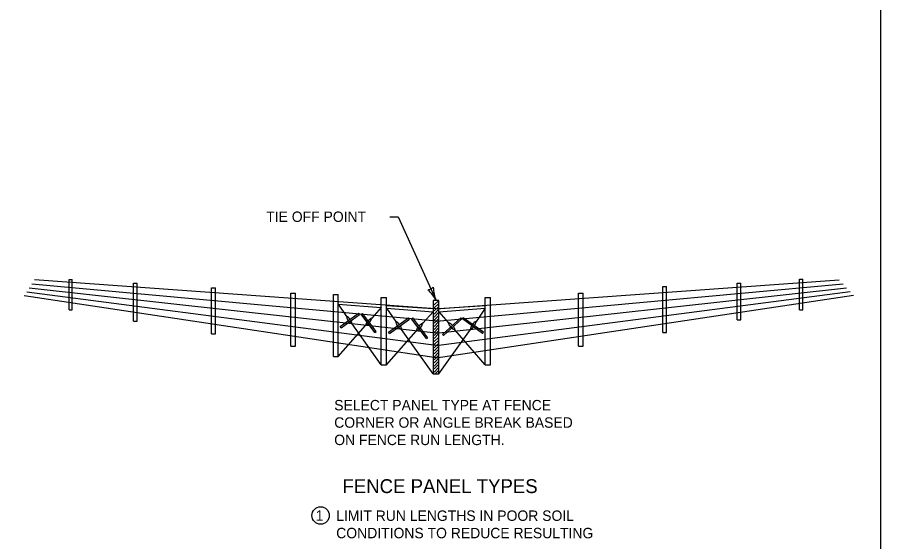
# Model space of a CAD drawing. Extents: x 49990.8 to 50021, y 49987.6 to 50011.4.
# Drawn here: x 50003.644 to 50008.615, y 50005.224 to 50008.243 of the extents above; entities that cross this region are included whole.
import ezdxf

# ---------------------------------------------------------------- set-up
doc = ezdxf.new("R2010")
doc.units = 0
for name, color, linetype in [('Level 1', 7, 'Continuous'), ('Level 2', 7, 'Continuous'), ('Level 3', 7, 'Continuous')]:
    doc.layers.add(name, color=color, linetype=linetype)

msp = doc.modelspace()

# ---------------------------------------------------------------- linework, layer by layer
at = {"layer": 'Level 1'}
for p, q in [((50006.0563, 50006.4939), (50003.7282, 50006.7067)), ((50006.0538, 50006.5643), (50003.7438, 50006.7306)), ((50003.9419, 50006.7341), (50003.9598, 50006.7341)), ((50003.9419, 50006.5579), (50003.9419, 50006.7341)), ((50003.9598, 50006.5579), (50003.9598, 50006.7341)), ((50004.3126, 50006.7133), (50004.3333, 50006.7133)), ((50004.3126, 50006.4931), (50004.3126, 50006.7133)), ((50004.3333, 50006.4931), (50004.3333, 50006.7133)), ((50006.0538, 50006.5643), (50008.3758, 50006.7315)), ((50006.0563, 50006.4939), (50008.3977, 50006.7082)), ((50007.7888, 50006.713), (50007.8086, 50006.713)), ((50007.7888, 50006.5019), (50007.7888, 50006.713)), ((50007.8086, 50006.5019), (50007.8086, 50006.713)), ((50008.1478, 50006.7348), (50008.1659, 50006.7348)), ((50008.1478, 50006.5587), (50008.1478, 50006.7348)), ((50008.1659, 50006.5587), (50008.1659, 50006.7348)), ((50006.0552, 50006.3532), (50003.6981, 50006.6608)), ((50006.0548, 50006.4238), (50003.7131, 50006.6837)), ((50004.7619, 50006.6855), (50004.7856, 50006.6855)), ((50004.7619, 50006.4214), (50004.7619, 50006.6855)), ((50004.7856, 50006.4214), (50004.7856, 50006.6855)), ((50005.2191, 50006.6553), (50005.2464, 50006.6553)), ((50005.2191, 50006.3503), (50005.2191, 50006.6553)), ((50005.2464, 50006.3503), (50005.2464, 50006.6553)), ((50006.0548, 50006.4238), (50008.4184, 50006.6861)), ((50006.0552, 50006.3532), (50008.4389, 50006.6643)), ((50006.8739, 50006.6553), (50006.9012, 50006.6553)), ((50006.8739, 50006.3503), (50006.8739, 50006.6553)), ((50006.9012, 50006.3503), (50006.9012, 50006.6553)), ((50007.3596, 50006.6926), (50007.3821, 50006.6926)), ((50007.3596, 50006.4291), (50007.3596, 50006.6926)), ((50007.3821, 50006.4291), (50007.3821, 50006.6926)), ((50006.0552, 50006.2831), (50003.6836, 50006.6387)), ((50005.4633, 50006.2907), (50005.4633, 50006.6471)), ((50005.4633, 50006.6471), (50005.492, 50006.6471)), ((50005.492, 50006.2907), (50005.492, 50006.6471)), ((50005.7386, 50006.6301), (50005.7698, 50006.6301)), ((50005.7386, 50006.2428), (50005.7386, 50006.6301)), ((50005.7698, 50006.2428), (50005.7698, 50006.6301)), ((50006.0714, 50006.6125), (50006.0379, 50006.6125)), ((50006.0379, 50006.6125), (50006.0379, 50006.19)), ((50006.044, 50006.5877), (50006.0681, 50006.6116)), ((50006.0552, 50006.2831), (50008.4583, 50006.6436)), ((50006.0714, 50006.19), (50006.0714, 50006.6125)), ((50006.3372, 50006.6301), (50006.3684, 50006.6301)), ((50006.3372, 50006.2428), (50006.3372, 50006.6301)), ((50006.3684, 50006.2428), (50006.3684, 50006.6301)), ((50003.9419, 50006.5579), (50003.9598, 50006.5579)), ((50005.492, 50006.5909), (50005.7386, 50006.5715)), ((50005.492, 50006.5909), (50005.5395, 50006.5214)), ((50005.7386, 50006.5715), (50005.684, 50006.5101)), ((50005.7698, 50006.5842), (50006.0379, 50006.5656)), ((50005.7698, 50006.5691), (50006.0379, 50006.548)), ((50005.7698, 50006.5691), (50005.8215, 50006.4935)), ((50006.0438, 50006.5346), (50006.0677, 50006.5585)), ((50006.044, 50006.5701), (50006.0681, 50006.594)), ((50006.044, 50006.5525), (50006.0681, 50006.5765)), ((50006.0538, 50006.5643), (50006.0538, 50006.5643)), ((50006.0714, 50006.5656), (50006.3372, 50006.5842)), ((50006.0714, 50006.5477), (50006.3372, 50006.5687)), ((50006.3372, 50006.5687), (50006.2869, 50006.4941)), ((50008.1478, 50006.5587), (50008.1659, 50006.5587)), ((50005.5026, 50006.4624), (50005.6086, 50006.5391)), ((50005.5077, 50006.4558), (50005.613, 50006.5329)), ((50005.613, 50006.5329), (50005.6086, 50006.5391)), ((50005.6242, 50006.5334), (50005.6305, 50006.5384)), ((50005.7031, 50006.429), (50005.6242, 50006.5334)), ((50005.7098, 50006.4336), (50005.6305, 50006.5384)), ((50005.7813, 50006.4293), (50005.8966, 50006.5127)), ((50005.7869, 50006.4221), (50005.9013, 50006.506)), ((50005.9013, 50006.506), (50005.8966, 50006.5127)), ((50005.9135, 50006.5066), (50005.9204, 50006.5119)), ((50005.9993, 50006.393), (50005.9135, 50006.5066)), ((50006.0066, 50006.398), (50005.9204, 50006.5119)), ((50006.0379, 50006.548), (50005.9785, 50006.4813)), ((50006.0438, 50006.5169), (50006.0677, 50006.5408)), ((50006.0438, 50006.4993), (50006.0677, 50006.5233)), ((50006.0438, 50006.4814), (50006.0677, 50006.5053)), ((50006.0714, 50006.5477), (50006.1248, 50006.4858)), ((50006.0914, 50006.4176), (50006.1976, 50006.5129)), ((50006.0976, 50006.4111), (50006.203, 50006.5065)), ((50006.203, 50006.5065), (50006.1976, 50006.5129)), ((50006.2068, 50006.5067), (50006.2115, 50006.5135)), ((50006.3217, 50006.4226), (50006.2068, 50006.5067)), ((50006.3273, 50006.4298), (50006.2115, 50006.5135)), ((50004.3126, 50006.4931), (50004.3333, 50006.4931)), ((50005.492, 50006.2907), (50005.6486, 50006.4689)), ((50005.5077, 50006.4558), (50005.5026, 50006.4624)), ((50005.7386, 50006.2422), (50005.5714, 50006.4774)), ((50006.0438, 50006.4638), (50006.0677, 50006.4877)), ((50006.0438, 50006.4461), (50006.0677, 50006.4701)), ((50006.0563, 50006.4939), (50006.0563, 50006.4939)), ((50007.7888, 50006.5019), (50007.8086, 50006.5019)), ((50004.7619, 50006.4214), (50004.7856, 50006.4214)), ((50005.7031, 50006.429), (50005.7098, 50006.4336)), ((50005.7698, 50006.2428), (50005.9401, 50006.4364)), ((50005.7869, 50006.4222), (50005.7813, 50006.4293)), ((50006.0379, 50006.19), (50005.8561, 50006.4456)), ((50006.0438, 50006.4292), (50006.0677, 50006.4532)), ((50006.0438, 50006.4117), (50006.0677, 50006.4356)), ((50006.0438, 50006.3941), (50006.0677, 50006.4179)), ((50006.0548, 50006.4238), (50006.0548, 50006.4238)), ((50006.0714, 50006.19), (50006.2523, 50006.4462)), ((50006.0976, 50006.4111), (50006.0914, 50006.4176)), ((50006.3372, 50006.2428), (50006.1642, 50006.4418)), ((50006.3217, 50006.4226), (50006.3273, 50006.4298)), ((50007.3596, 50006.4291), (50007.3821, 50006.4291)), ((50005.9993, 50006.393), (50006.0066, 50006.398)), ((50006.044, 50006.3763), (50006.068, 50006.4002)), ((50006.044, 50006.3587), (50006.068, 50006.3827)), ((50006.044, 50006.341), (50006.068, 50006.365)), ((50005.2191, 50006.3503), (50005.2464, 50006.3503)), ((50006.0438, 50006.3224), (50006.0677, 50006.3465)), ((50006.0438, 50006.3048), (50006.0677, 50006.3289)), ((50006.0438, 50006.2871), (50006.0677, 50006.3113)), ((50006.0552, 50006.3532), (50006.0552, 50006.3532)), ((50006.8739, 50006.3503), (50006.9012, 50006.3503)), ((50005.4633, 50006.2907), (50005.492, 50006.2907)), ((50006.0438, 50006.2707), (50006.0677, 50006.2946)), ((50006.0438, 50006.2531), (50006.0677, 50006.2769)), ((50006.0438, 50006.2354), (50006.0677, 50006.2594)), ((50006.0552, 50006.2831), (50006.0552, 50006.2831)), ((50005.7386, 50006.2428), (50005.7698, 50006.2428)), ((50006.0438, 50006.2186), (50006.0677, 50006.2424)), ((50006.0438, 50006.2009), (50006.0677, 50006.2249)), ((50006.0519, 50006.1914), (50006.0677, 50006.2073)), ((50006.3372, 50006.2428), (50006.3684, 50006.2428)), ((50006.0379, 50006.19), (50006.0714, 50006.19))]:
    msp.add_line(p, q, dxfattribs=at)
msp.add_lwpolyline([(50008.6146, 50011.2628), (50000.3356, 50011.2628), (50000.3356, 50000.0624), (50008.6146, 50000.0624)], close=True, dxfattribs=at)
for centre, radius, start, end in [((50005.599, 50006.5309), 0.0603, 189.0887, 242.6916), ((50005.5119, 50006.4678), 0.0603, 36.8605, 62.6916), ((50005.6255, 50006.5246), 0.0603, 292.5657, 346.1686), ((50005.7071, 50006.4545), 0.0603, 112.5657, 137.0992), ((50005.5119, 50006.4678), 0.0603, 9.0887, 29.2821), ((50005.7071, 50006.4545), 0.0603, 144.9913, 166.1686), ((50005.8862, 50006.5038), 0.0655, 189.0887, 242.6916), ((50005.7914, 50006.4353), 0.0655, 36.8605, 62.6916), ((50005.7914, 50006.4353), 0.0655, 9.0887, 29.2821), ((50005.9149, 50006.4969), 0.0655, 292.5657, 346.1686), ((50006.0037, 50006.4208), 0.0655, 144.9913, 166.1686), ((50006.0037, 50006.4208), 0.0655, 112.5657, 137.0992), ((50006.1881, 50006.5028), 0.0655, 195.0597, 248.6626), ((50006.101, 50006.4248), 0.0655, 42.8063, 68.6626), ((50006.101, 50006.4248), 0.0655, 15.0597, 35.225), ((50006.2222, 50006.5044), 0.0655, 297.3084, 350.9113), ((50006.3169, 50006.4359), 0.0655, 150.7338, 170.9113), ((50006.3169, 50006.4359), 0.0655, 117.3084, 143.1471)]:
    msp.add_arc(centre, radius, start, end, dxfattribs=at)
at = {"layer": 'Level 2'}
msp.add_circle((50005.3899, 50005.3747), 0.05, dxfattribs=at)
at = {"layer": 'Level 3'}
for p, q in [((50005.7893, 50007.0949), (50005.8367, 50007.0949)), ((50005.8367, 50007.0949), (50006.0547, 50006.6125))]:
    msp.add_line(p, q, dxfattribs=at)
for centre, radius, start, end in [((50006.0019, 50006.7293), 0.0548, 276.4549, 312.1772), ((50005.8473, 50006.5062), 0.233, 27.1434, 46.3932), ((50006.2609, 50006.6956), 0.2223, 181.7721, 201.9556)]:
    msp.add_arc(centre, radius, start, end, dxfattribs=at)

# ---------------------------------------------------------------- texts
at = {"layer": 'Level 2'}
for s, height, p in [('TIE OFF POINT', 0.06, (50005.077, 50007.0649)), ('SELECT PANEL TYPE AT FENCE', 0.06, (50005.4684, 50005.98)), ('CORNER OR ANGLE BREAK BASED', 0.06, (50005.4684, 50005.88)), ('ON FENCE RUN LENGTH.', 0.06, (50005.4684, 50005.78)), ('FENCE PANEL TYPES', 0.08, (50005.516, 50005.5037)), ('1', 0.06, (50005.3616, 50005.3447)), ('LIMIT RUN LENGTHS IN POOR SOIL', 0.06, (50005.4799, 50005.3437)), ('CONDITIONS TO REDUCE RESULTING ', 0.06, (50005.4799, 50005.2437))]:
    msp.add_text(s, height=height, dxfattribs=at).set_placement(p)

doc.saveas('drawing.dxf')
